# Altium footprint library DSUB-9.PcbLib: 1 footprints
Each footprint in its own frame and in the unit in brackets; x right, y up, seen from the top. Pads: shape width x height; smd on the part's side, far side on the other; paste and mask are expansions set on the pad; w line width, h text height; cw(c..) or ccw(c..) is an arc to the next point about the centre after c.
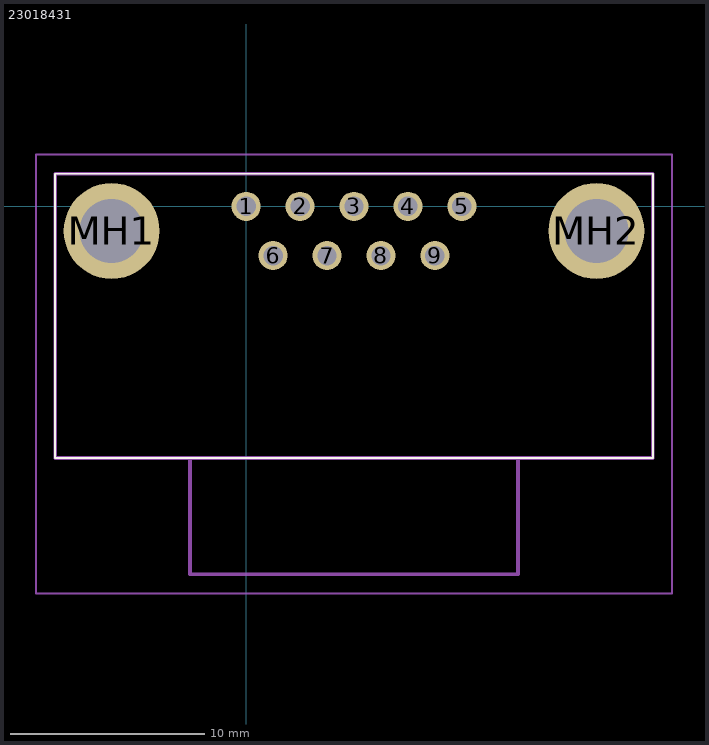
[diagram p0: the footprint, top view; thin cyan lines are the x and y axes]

## 23018431 [mm]
pads (11):
  round 1.5 hole 1: 1(0,0) 2(2.78,0) 3(5.56,0) 4(8.34,0) 5(11.12,0) 6(1.39,-2.54) 7(4.17,-2.54) 8(6.95,-2.54) 9(9.73,-2.54)
  round 4.95 hole 3.3: MH1(-6.935,-1.27) MH2(18.055,-1.27)
Top Overlay:
  lines w0.1: -9.845,-12.97 -9.845,1.68 20.965,1.68 20.965,-12.97 -9.845,-12.97
Mechanical 13:
  lines w0.2: -2.89,-12.97 -2.89,-18.97 14.01,-18.97 14.01,-12.97 ; -9.845,-12.97 -9.845,1.68 20.965,1.68 20.965,-12.97 -9.845,-12.97
Mechanical 15:
  lines w0.1: -10.845,-19.97 -10.845,2.68 21.965,2.68 21.965,-19.97 -10.845,-19.97
3D body "2301843-1.stp": height 13.59, standoff -3.79, extent -9.855,-18.95 20.955,1.7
